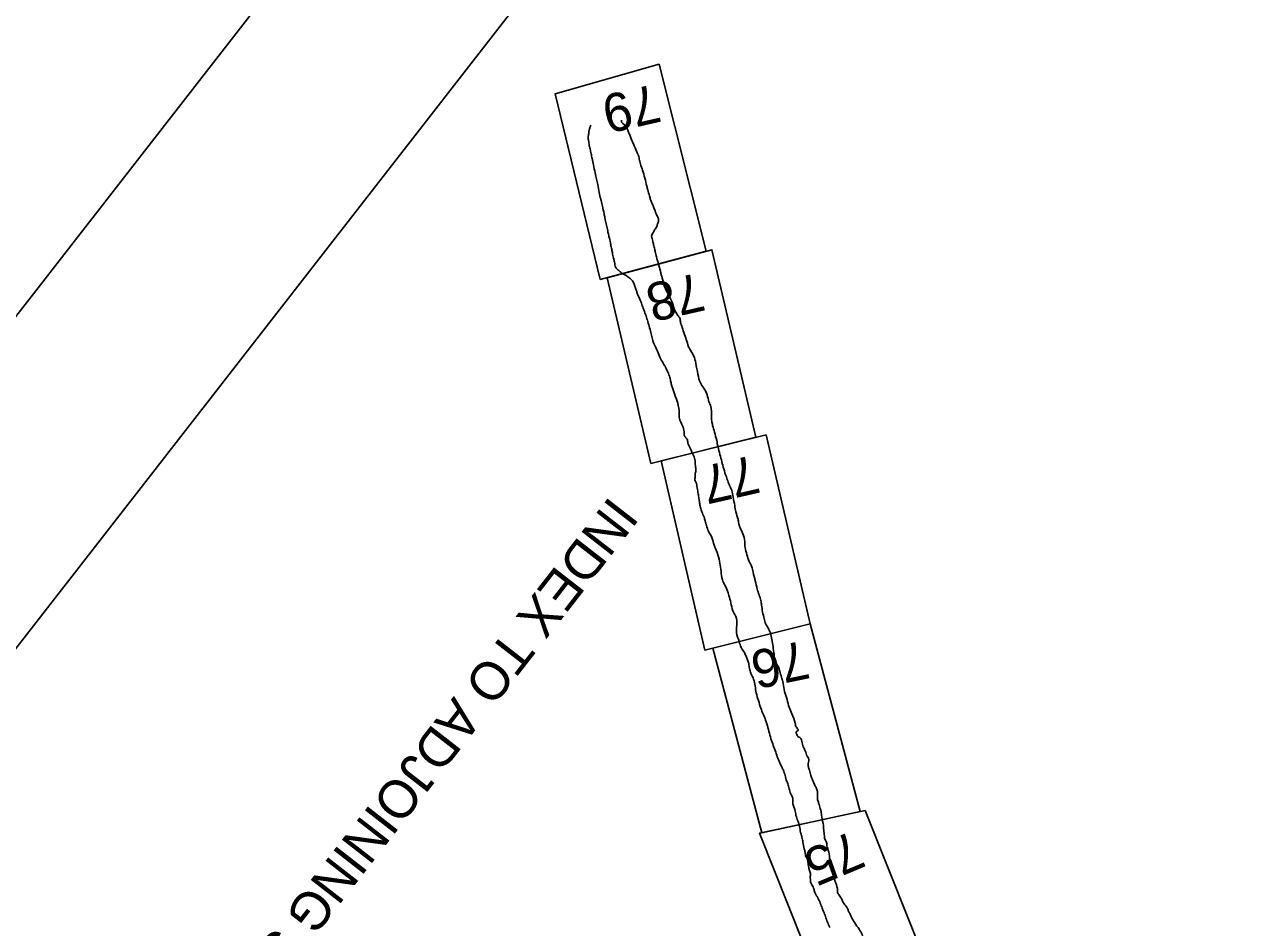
# Model space of a CAD drawing. Extents: x 3888273 to 3909528, y 158682 to 181032.
# Drawn here: x 3892136 to 3894021, y 170048 to 171432 of the extents above; entities that cross this region are included whole.
import ezdxf

# ---------------------------------------------------------------- set-up
doc = ezdxf.new("R2010")
doc.units = 0
for name, color, linetype in [('G-ANNO-NPLT', 7, 'Continuous'), ('V-ANNO-NPLT', 7, 'Continuous'), ('V-ANNO-SYMB', 7, 'Continuous')]:
    doc.layers.add(name, color=color, linetype=linetype)

msp = doc.modelspace()

# ---------------------------------------------------------------- linework, layer by layer
at = {"layer": 'G-ANNO-NPLT'}
msp.add_lwpolyline([(3899761, 180802.2), (3888502.9, 166332.7), (3898039.6, 158912.6), (3909297.7, 173382)], close=True, dxfattribs=at)
at = {"layer": 'V-ANNO-NPLT'}
msp.add_line((3893180.5, 171084.2), (3893018.1, 171040.8), dxfattribs=at)
for points in [[(3893180.5, 171084.2), (3893108.6, 171371), (3892949.5, 171325.8), (3893018.1, 171040.8)], [(3893256.9, 170799.1), (3893189.6, 171086.6), (3893029, 171043.7)], [(3893029, 171043.7), (3893095.7, 170758.8)], [(3893256.9, 170799.1), (3893095.7, 170758.8)], [(3893272.4, 170803), (3893111.6, 170762.8), (3893178.5, 170472.9)], [(3893340.1, 170513.3), (3893272.4, 170803)], [(3893178.5, 170472.9), (3893340.1, 170513.3)], [(3893340.1, 170513.3), (3893191, 170476.1)], [(3893340.1, 170513.3), (3893416.9, 170225.5)], [(3893191, 170476.1), (3893266.1, 170192.9)], [(3893424.1, 170227), (3893262.3, 170192.1), (3893375.3, 169908.7)], [(3893416.9, 170225.5), (3893266.1, 170192.9)], [(3893526.9, 169969.3), (3893424.1, 170227)]]:
    msp.add_lwpolyline(points, dxfattribs=at)
for points in [[(3893074.8, 171235.1), (3893070.5, 171245.7), (3893067.8, 171251.8), (3893065.2, 171258.1), (3893062.9, 171264.1), (3893060.4, 171269.9), (3893058.6, 171274.7), (3893057.5, 171275.8), (3893055.3, 171278), (3893052.1, 171281.1), (3893051.1, 171282.1), (3893050.8, 171283.4), (3893050.8, 171285.1)], [(3893006, 171226.3), (3893004.3, 171233.7), (3893002.8, 171241.3), (3893001.3, 171248.3), (3893000.7, 171252.5), (3892999.7, 171257.6), (3893000.4, 171263.4), (3893001.2, 171269.1), (3893002.6, 171274.2), (3893003.8, 171277.6)], [(3893019, 171164.4), (3893016.9, 171174.2), (3893014.5, 171186.4), (3893012.8, 171194.7), (3893010.5, 171204.4), (3893008, 171216.5), (3893006, 171226.3)], [(3893089.6, 171184.1), (3893086.7, 171196.1), (3893083.2, 171208.4), (3893080, 171218), (3893078.2, 171225.5), (3893076.1, 171232.9), (3893074.8, 171235.1)], [(3893106.2, 171125.8), (3893107.6, 171131.2), (3893107.5, 171133.8), (3893105.3, 171139.1), (3893102.4, 171146), (3893100, 171152.4), (3893097.4, 171158.4), (3893095.5, 171163.3), (3893093.8, 171169.2), (3893091.2, 171178.2), (3893089.6, 171184.1)], [(3893033.9, 171097), (3893031.7, 171107), (3893030.2, 171113.5), (3893028.5, 171122.4), (3893026.4, 171130.6), (3893025.6, 171135.4), (3893024.2, 171141.8), (3893021.9, 171153.4), (3893019.7, 171161.9), (3893019, 171164.4)], [(3893107.5, 171065), (3893106.4, 171068.7), (3893105, 171073.8), (3893104.2, 171077.5), (3893102.9, 171081.8), (3893101.9, 171087.2), (3893100.2, 171094.3), (3893098.9, 171099.9), (3893098.1, 171103.7), (3893097.1, 171107.2), (3893099.9, 171113.3), (3893102.3, 171118.1), (3893104.3, 171121.4), (3893106.2, 171125.8)], [(3893052, 171050.2), (3893048, 171053.7), (3893043.9, 171057.2), (3893042.2, 171059.5), (3893040.2, 171067.3), (3893038.6, 171073.7), (3893037, 171082.2), (3893035.6, 171089), (3893034, 171096.4), (3893033.9, 171097)], [(3893113, 171044.4), (3893111.6, 171049.2), (3893110.5, 171053.9), (3893107.5, 171065)], [(3893081.4, 171004.7), (3893077.6, 171014.2), (3893074.9, 171020.2), (3893073.5, 171024.7), (3893071.1, 171030.8), (3893070.4, 171033.7), (3893052, 171050.2)], [(3893164.7, 170912.7), (3893161.5, 170924), (3893155.6, 170934.4), (3893153.8, 170938), (3893150.2, 170949.1), (3893146.5, 170959.5), (3893143.2, 170969.9), (3893141.1, 170976.8), (3893140.3, 170981.8), (3893137.2, 170986), (3893128, 171007.2), (3893119.5, 171024.3), (3893115.6, 171033.7), (3893114.6, 171038.3), (3893113, 171044.4)], [(3893123.7, 170894.6), (3893119.4, 170904.5), (3893110.2, 170920.9), (3893106, 170931.3), (3893100.1, 170943.8), (3893095.8, 170959.8), (3893090.6, 170978.7), (3893087.8, 170987.4), (3893084.1, 170996.9), (3893081.4, 171004.7)], [(3893196.8, 170794.4), (3893193.5, 170807.1), (3893190.6, 170817.4), (3893189.2, 170823.9), (3893188.6, 170831.5), (3893187.8, 170846.4), (3893185, 170853.5), (3893182.2, 170864.3), (3893176.9, 170874.3), (3893171.8, 170882.4), (3893168, 170895.8), (3893164.7, 170912.7)], [(3893160.1, 170773), (3893154.6, 170785.5), (3893152.6, 170790.2), (3893151.5, 170796), (3893147.9, 170800.3), (3893146.6, 170809.8), (3893139.8, 170827.8), (3893139.4, 170836.1), (3893137, 170851.4), (3893128.4, 170876.6), (3893127.2, 170881.1), (3893125.8, 170887.1), (3893123.7, 170894.6)], [(3893220.2, 170717.8), (3893217.2, 170723.4), (3893214.5, 170730.5), (3893211.6, 170738.6), (3893207.6, 170750.7), (3893201.8, 170772.8), (3893198.8, 170784.5), (3893196.8, 170794.6)], [(3893169.6, 170705.7), (3893169.4, 170706.8), (3893168.1, 170714.5), (3893166.6, 170723.7), (3893165.7, 170728.1), (3893163.8, 170732.3), (3893163.7, 170739.4), (3893163.8, 170743.9), (3893164.7, 170746.7), (3893164.4, 170753.5), (3893164, 170757.9), (3893163.5, 170765), (3893160.1, 170773)], [(3893113.6, 170763.4), (3893113.3, 170762.9), (3893112.8, 170762.7), (3893112.4, 170762.4), (3893111.8, 170762.2)], [(3893279, 170499.3), (3893275.5, 170506.6), (3893271.5, 170513.5), (3893269.5, 170521.1), (3893267.2, 170531), (3893265.6, 170541.9), (3893264.5, 170548.7), (3893258.9, 170566.4), (3893255.9, 170579.2), (3893252.5, 170592.2), (3893250.3, 170601.4), (3893246.6, 170608.7), (3893243.1, 170619), (3893240.3, 170630.1), (3893239.7, 170639.4), (3893236.8, 170651.3), (3893230.7, 170666.6), (3893230.2, 170670.6), (3893229.5, 170673.4), (3893226.3, 170684.9), (3893224.4, 170694.5), (3893222.2, 170707.3), (3893220.2, 170717.8)], [(3893169.6, 170705.7), (3893170.5, 170698.8), (3893172, 170691.6), (3893174.1, 170684.7), (3893177.5, 170676.9)], [(3893181.2, 170663.8), (3893179.2, 170670.9), (3893177.5, 170676.9)], [(3893231.3, 170486.1), (3893227.3, 170499.9), (3893227, 170521.5), (3893221.7, 170533.1), (3893218.4, 170545.4), (3893215.5, 170556.5), (3893209.3, 170572.6), (3893205.6, 170580.8), (3893203.4, 170593.6), (3893201.7, 170606), (3893198.7, 170618.8), (3893193, 170633.6), (3893189.3, 170645.5), (3893184.1, 170655.4), (3893181.2, 170663.8)], [(3893317.3, 170360.7), (3893312, 170375.1), (3893307.8, 170385.2), (3893304.7, 170397.4), (3893300.7, 170409.5), (3893298.5, 170421.9), (3893293.4, 170440.6), (3893291.3, 170447.2), (3893286.8, 170455.7), (3893284.8, 170466.2), (3893283.1, 170478.2), (3893281.4, 170489.2), (3893279, 170499.3)], [(3893297.2, 170292.6), (3893292.5, 170302.4), (3893285.5, 170321.3), (3893281.7, 170331.7), (3893278.3, 170342.5), (3893271.8, 170365.6), (3893264.4, 170383.7), (3893260.9, 170395.5), (3893257.4, 170407.2), (3893253.4, 170428.3), (3893249.3, 170437.3), (3893247.1, 170444.7), (3893245.9, 170452.2), (3893243.9, 170457.9), (3893239.2, 170469), (3893234.3, 170477), (3893231.3, 170486.1)], [(3893327.8, 170330.5), (3893324.4, 170338.7), (3893321.7, 170340.1), (3893320.9, 170341), (3893319.7, 170343.4), (3893318.9, 170345.3), (3893318.4, 170347), (3893318.5, 170347.6), (3893321, 170349.1), (3893321.4, 170349.8), (3893319, 170354.6), (3893317.2, 170360.5)], [(3893350.3, 170259.3), (3893347.9, 170264.5), (3893343.8, 170274), (3893340.9, 170280.8), (3893338.8, 170288.7), (3893337.3, 170293.8), (3893337.1, 170299), (3893337.8, 170303.4), (3893337.4, 170307.1), (3893335.5, 170310.3), (3893332.5, 170318.3), (3893330.1, 170323.2), (3893329, 170326.5), (3893327.8, 170330.5)], [(3893331.1, 170168.2), (3893328.9, 170178.6), (3893327.5, 170185.9), (3893326, 170191), (3893324.1, 170200.4), (3893321.1, 170211.3), (3893318.3, 170219.6), (3893316.4, 170228.4), (3893314.3, 170234.1), (3893313.6, 170240.8), (3893313.3, 170246), (3893310.1, 170253.1), (3893308.1, 170260.3), (3893305.7, 170267.8), (3893303.5, 170274.1), (3893301, 170282.7), (3893299.8, 170286.6), (3893297.2, 170292.6)], [(3893350.3, 170259.3), (3893351.5, 170253), (3893351.2, 170248.8), (3893351.5, 170243.7), (3893353, 170238.5)], [(3893360.5, 170204), (3893357.9, 170217.3), (3893356.7, 170225.5), (3893354.2, 170234.3), (3893353, 170238.5)], [(3893399, 170072.4), (3893395.8, 170079.3), (3893391, 170085.4), (3893388.4, 170091.1), (3893384.5, 170097.4), (3893382.1, 170101.1), (3893381.7, 170107.2), (3893381.1, 170110.4), (3893377.2, 170121.1), (3893374.9, 170131), (3893374.2, 170136.1), (3893372.2, 170142.6), (3893370.3, 170151.3), (3893369.5, 170156.9), (3893366.9, 170169.3), (3893365.8, 170172.8), (3893365.6, 170176.5), (3893362.7, 170182.9), (3893361.7, 170190), (3893360.7, 170199.3), (3893360.5, 170204)], [(3893370, 170047.8), (3893366.6, 170055.9), (3893363.5, 170064.7), (3893360.5, 170072), (3893358.4, 170077.3), (3893355.6, 170084.9), (3893351.1, 170094.3), (3893348.8, 170098), (3893346.8, 170102.8), (3893345.2, 170108.1), (3893341.8, 170114.9), (3893340.7, 170117.5), (3893340.3, 170121.9), (3893339.9, 170125.8), (3893340.7, 170129.1), (3893339.1, 170134.9), (3893337.9, 170139.5), (3893336.5, 170147.7), (3893335.8, 170151.9), (3893333.7, 170155.8), (3893332.2, 170162.9), (3893331.1, 170168.2)], [(3893448.8, 169938.2), (3893445.2, 169953.8), (3893442.5, 169967.3), (3893439.6, 169979.1), (3893437, 169990.7), (3893432.3, 170004), (3893429, 170013.8), (3893424.6, 170023.9), (3893422, 170026.6), (3893420.7, 170033), (3893419.6, 170036.8), (3893415.1, 170045.2), (3893408.5, 170054.7), (3893399, 170072.4)]]:
    msp.add_spline(points, degree=3, dxfattribs=at)
at = {"layer": 'V-ANNO-SYMB'}
msp.add_lwpolyline([(3899163.3, 179525), (3889005.4, 166469.6), (3898048.8, 159433.3), (3908206.7, 172488.7), (3899163.3, 179525)], dxfattribs=at)

# ---------------------------------------------------------------- texts
at = {"layer": 'V-ANNO-NPLT'}
for s, height, rotation, p in [('79', 58.5, 192.8267, (3893102.1, 171340.9)), ('78', 58.5, 192.8267, (3893169.6, 171051.7)), ('77', 58.5, 192.8267, (3893253.7, 170772.3)), ('INDEX TO ADJOINING SHEETS', 58.33, 232.1148, (3893033.8, 170710.8)), ('76', 58.5, 191.8267, (3893330.8, 170487.9)), ('75', 58.5, 202.8267, (3893405.8, 170197))]:
    msp.add_text(s, height=height, rotation=rotation, dxfattribs=at).set_placement(p)

doc.saveas('drawing.dxf')
